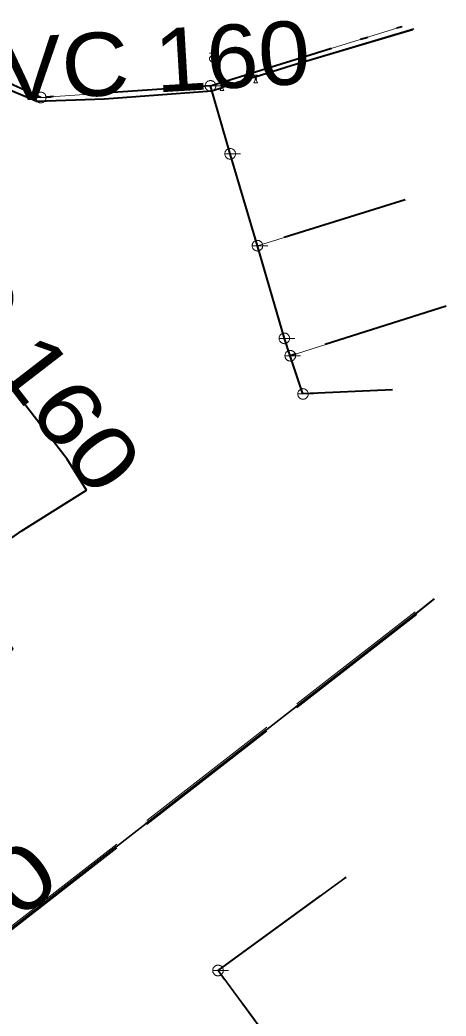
# Model space of a CAD drawing. Extents: x -968691 to -140888, y -1376050 to -879856.
# Drawn here: x -647528.6 to -647447.9, y -1059078.7 to -1058890.1 of the extents above; entities that cross this region are included whole.
import ezdxf
from ezdxf.enums import TextEntityAlignment as Align

# ---------------------------------------------------------------- set-up
doc = ezdxf.new("R2010")
doc.units = 0
doc.header["$LTSCALE"] = 4.8
doc.linetypes.add('DASH_DOUBLE_DOT', pattern=[9.2, 5, -1.2, 0.3, -1.2, 0.3, -1.2])
doc.linetypes.add('LONG_DASHED', pattern=[7.5, 6, -1.5])
doc.layers.add('1', color=7, linetype='Continuous', lineweight=13)

msp = doc.modelspace()

# ---------------------------------------------------------------- hatches: boundary and pattern name
at = {"layer": '1'}
for points in [[(-647490.228, -1058902.72), (-647490.23, -1058902.696), (-647490.237, -1058902.673), (-647490.247, -1058902.651), (-647490.261, -1058902.632), (-647490.279, -1058902.615), (-647490.299, -1058902.602), (-647490.322, -1058902.593), (-647490.345, -1058902.589), (-647490.369, -1058902.588), (-647490.393, -1058902.592), (-647490.416, -1058902.6), (-647490.437, -1058902.612), (-647490.455, -1058902.628), (-647490.47, -1058902.647), (-647490.482, -1058902.668), (-647490.489, -1058902.691), (-647490.492, -1058902.715), (-647490.491, -1058902.739), (-647490.485, -1058902.762), (-647490.475, -1058902.784), (-647490.462, -1058902.804), (-647490.445, -1058902.821), (-647490.425, -1058902.835), (-647490.403, -1058902.845), (-647490.38, -1058902.851), (-647490.356, -1058902.852), (-647490.332, -1058902.849), (-647490.309, -1058902.842), (-647490.288, -1058902.831), (-647490.269, -1058902.816), (-647490.253, -1058902.797), (-647490.241, -1058902.777), (-647490.232, -1058902.754), (-647490.228, -1058902.73)], [(-647483.822, -1058901.276), (-647483.824, -1058901.252), (-647483.831, -1058901.229), (-647483.841, -1058901.207), (-647483.855, -1058901.188), (-647483.873, -1058901.171), (-647483.893, -1058901.158), (-647483.916, -1058901.149), (-647483.939, -1058901.145), (-647483.963, -1058901.144), (-647483.987, -1058901.148), (-647484.01, -1058901.156), (-647484.031, -1058901.168), (-647484.049, -1058901.184), (-647484.064, -1058901.203), (-647484.076, -1058901.224), (-647484.083, -1058901.247), (-647484.086, -1058901.271), (-647484.085, -1058901.295), (-647484.079, -1058901.318), (-647484.069, -1058901.34), (-647484.056, -1058901.36), (-647484.039, -1058901.377), (-647484.019, -1058901.391), (-647483.997, -1058901.401), (-647483.974, -1058901.407), (-647483.95, -1058901.408), (-647483.926, -1058901.405), (-647483.903, -1058901.398), (-647483.882, -1058901.387), (-647483.863, -1058901.372), (-647483.847, -1058901.353), (-647483.835, -1058901.333), (-647483.826, -1058901.31), (-647483.822, -1058901.286)]]:
    msp.add_hatch(color=256, dxfattribs=at).paths.add_polyline_path(points)

# ---------------------------------------------------------------- linework, layer by layer
at = {"layer": '1', "linetype": 'DASH_DOUBLE_DOT', "lineweight": 40}
for p, q in [((-647492.53, -1058902.58), (-647456.24, -1058891.31)), ((-647492.15, -1058897.44), (-647490.36, -1058902.72)), ((-647484.085, -1058900.877), (-647490.306, -1058902.873)), ((-647484.085, -1058900.877), (-647483.954, -1058901.276)), ((-647488.8, -1058915.44), (-647492.53, -1058902.58)), ((-647490.36, -1058902.72), (-647490.306, -1058902.873)), ((-647483.64, -1058932.83), (-647488.8, -1058915.44)), ((-647455.68, -1058924.12), (-647483.64, -1058932.83)), ((-647478.54, -1058950.37), (-647483.64, -1058932.83)), ((-647447.92, -1058944.26), (-647477.42, -1058953.66)), ((-647477.42, -1058953.66), (-647478.54, -1058950.37)), ((-647475.01, -1058960.9), (-647477.42, -1058953.66)), ((-647458.04, -1058960.1), (-647475.01, -1058960.9))]:
    msp.add_line(p, q, dxfattribs=at)
at = {"layer": '1'}
for p, q in [((-647492.53, -1058902.58), (-647456.24, -1058891.31)), ((-647492.709, -1058896.37), (-647491.591, -1058896.37)), ((-647492.15, -1058896.882), (-647492.15, -1058896.37)), ((-647492.15, -1058897.44), (-647490.36, -1058902.72)), ((-647484.085, -1058900.877), (-647483.954, -1058901.276)), ((-647493.538, -1058902.58), (-647490.562, -1058902.58)), ((-647488.8, -1058915.44), (-647492.53, -1058902.58)), ((-647490.36, -1058902.72), (-647490.306, -1058902.873)), ((-647525.668, -1058904.78), (-647522.692, -1058904.78)), ((-647489.808, -1058915.44), (-647486.832, -1058915.44)), ((-647483.64, -1058932.83), (-647488.8, -1058915.44)), ((-647455.68, -1058924.12), (-647483.64, -1058932.83)), ((-647484.648, -1058932.83), (-647481.672, -1058932.83)), ((-647478.54, -1058950.37), (-647483.64, -1058932.83)), ((-647447.92, -1058944.26), (-647477.42, -1058953.66)), ((-647479.548, -1058950.37), (-647476.572, -1058950.37)), ((-647477.42, -1058953.66), (-647478.54, -1058950.37)), ((-647478.428, -1058953.66), (-647475.452, -1058953.66)), ((-647475.01, -1058960.9), (-647477.42, -1058953.66)), ((-647476.018, -1058960.9), (-647473.042, -1058960.9)), ((-647458.04, -1058960.1), (-647475.01, -1058960.9)), ((-647492.108, -1059070.03), (-647489.132, -1059070.03))]:
    msp.add_line(p, q, dxfattribs=at)
at = {"layer": '1', "lineweight": 35}
msp.add_line((-647484.085, -1058900.877), (-647490.306, -1058902.873), dxfattribs=at)
at = {"layer": '1', "linetype": 'LONG_DASHED'}
for p, q in [((-647646.574, -1059152.253), (-647453.794, -1059002.143)), ((-647453.426, -1059002.617), (-647646.206, -1059152.727))]:
    msp.add_line(p, q, dxfattribs=at)
at = {"layer": '1', "linetype": 'DASH_DOUBLE_DOT', "lineweight": 40}
for points in [[(-647484.085, -1058900.877), (-647477.27, -1058898.69), (-647454, -1058891.81)], [(-647492.53, -1058902.58), (-647524.66, -1058904.78), (-647542.07, -1058897.06)], [(-647562.952, -1058916.613), (-647541.39, -1058898.8), (-647525.39, -1058905.47), (-647512.6, -1058905.03), (-647492.29, -1058903.51), (-647490.306, -1058902.873)], [(-647532.092, -1059010.546), (-647529.959, -1059009.197), (-647539.29, -1058995.84), (-647539.66, -1058995.19), (-647539.24, -1058994.56), (-647537.46, -1058993.28), (-647528.4, -1058986.88), (-647516.03, -1058979.12), (-647519.65, -1058973.26), (-647530.64, -1058959.05), (-647535.07, -1058953.43), (-647549.25, -1058935.34), (-647563.74, -1058917.26), (-647562.952, -1058916.613)], [(-647489.07, -1059108.78), (-647472.19, -1059095.7), (-647491.1, -1059070.03), (-647466.86, -1059052.34)]]:
    msp.add_lwpolyline(points, dxfattribs=at)
at = {"layer": '1', "lineweight": 35}
for points in [[(-647484.085, -1058900.877), (-647477.27, -1058898.69), (-647454, -1058891.81)], [(-647562.952, -1058916.613), (-647541.39, -1058898.8), (-647525.39, -1058905.47), (-647512.6, -1058905.03), (-647492.29, -1058903.51), (-647490.306, -1058902.873)], [(-647532.092, -1059010.546), (-647529.959, -1059009.197), (-647539.29, -1058995.84), (-647539.66, -1058995.19), (-647539.24, -1058994.56), (-647537.46, -1058993.28), (-647528.4, -1058986.88), (-647516.03, -1058979.12), (-647519.65, -1058973.26), (-647530.64, -1058959.05), (-647535.07, -1058953.43), (-647549.25, -1058935.34), (-647563.74, -1058917.26), (-647562.952, -1058916.613)], [(-647450.19, -1058999.69), (-647453.61, -1059002.38), (-647646.39, -1059152.49), (-647646.64, -1059152.7), (-647649.55, -1059154.88)], [(-647495.05, -1059100.76), (-647489.07, -1059108.78), (-647472.19, -1059095.7), (-647491.1, -1059070.03), (-647466.86, -1059052.34)]]:
    msp.add_lwpolyline(points, dxfattribs=at)
at = {"layer": '1'}
msp.add_lwpolyline([(-647492.53, -1058902.58), (-647524.66, -1058904.78), (-647542.07, -1058897.06)], dxfattribs=at)
for points in [[(-647491.591, -1058897.44), (-647491.6, -1058897.341), (-647491.627, -1058897.244), (-647491.671, -1058897.154), (-647491.73, -1058897.072), (-647491.802, -1058897.003), (-647491.886, -1058896.948), (-647491.978, -1058896.909), (-647492.076, -1058896.887), (-647492.176, -1058896.882), (-647492.276, -1058896.896), (-647492.371, -1058896.927), (-647492.459, -1058896.975), (-647492.538, -1058897.038), (-647492.603, -1058897.114), (-647492.654, -1058897.2), (-647492.689, -1058897.294), (-647492.707, -1058897.393), (-647492.706, -1058897.493), (-647492.688, -1058897.592), (-647492.652, -1058897.686), (-647492.6, -1058897.771), (-647492.534, -1058897.847), (-647492.455, -1058897.909), (-647492.366, -1058897.956), (-647492.271, -1058897.986), (-647492.171, -1058897.999), (-647492.071, -1058897.994), (-647491.973, -1058897.971), (-647491.881, -1058897.93), (-647491.798, -1058897.875), (-647491.726, -1058897.805), (-647491.668, -1058897.723), (-647491.625, -1058897.632), (-647491.599, -1058897.535)], [(-647484.304, -1058900.526), (-647483.604, -1058900.526), (-647484.304, -1058902.026), (-647483.604, -1058902.026)], [(-647492.53, -1058901.572), (-647492.635, -1058901.578), (-647492.739, -1058901.594), (-647492.841, -1058901.622), (-647492.94, -1058901.66), (-647493.034, -1058901.707), (-647493.122, -1058901.765), (-647493.204, -1058901.831), (-647493.279, -1058901.906), (-647493.345, -1058901.988), (-647493.403, -1058902.076), (-647493.45, -1058902.17), (-647493.488, -1058902.269), (-647493.516, -1058902.371), (-647493.532, -1058902.475), (-647493.538, -1058902.58), (-647493.532, -1058902.685), (-647493.516, -1058902.79), (-647493.488, -1058902.892), (-647493.45, -1058902.99), (-647493.403, -1058903.084), (-647493.345, -1058903.173), (-647493.279, -1058903.255), (-647493.204, -1058903.329), (-647493.122, -1058903.395), (-647493.034, -1058903.453), (-647492.94, -1058903.501), (-647492.841, -1058903.539), (-647492.739, -1058903.566), (-647492.635, -1058903.582), (-647492.53, -1058903.588), (-647492.425, -1058903.582), (-647492.32, -1058903.566), (-647492.218, -1058903.539), (-647492.12, -1058903.501), (-647492.026, -1058903.453), (-647491.937, -1058903.395), (-647491.855, -1058903.329), (-647491.781, -1058903.255), (-647491.715, -1058903.173), (-647491.657, -1058903.084), (-647491.609, -1058902.99), (-647491.571, -1058902.892), (-647491.544, -1058902.79), (-647491.528, -1058902.685), (-647491.522, -1058902.58), (-647491.528, -1058902.475), (-647491.544, -1058902.371), (-647491.571, -1058902.269), (-647491.609, -1058902.17), (-647491.657, -1058902.076), (-647491.715, -1058901.988), (-647491.781, -1058901.906), (-647491.855, -1058901.831), (-647491.937, -1058901.765), (-647492.026, -1058901.707), (-647492.12, -1058901.66), (-647492.218, -1058901.622), (-647492.32, -1058901.594), (-647492.425, -1058901.578)], [(-647490.71, -1058901.97), (-647490.01, -1058901.97), (-647490.71, -1058903.47), (-647490.01, -1058903.47)], [(-647490.228, -1058902.72), (-647490.23, -1058902.696), (-647490.237, -1058902.673), (-647490.247, -1058902.651), (-647490.261, -1058902.632), (-647490.279, -1058902.615), (-647490.299, -1058902.602), (-647490.322, -1058902.593), (-647490.345, -1058902.589), (-647490.369, -1058902.588), (-647490.393, -1058902.592), (-647490.416, -1058902.6), (-647490.437, -1058902.612), (-647490.455, -1058902.628), (-647490.47, -1058902.647), (-647490.482, -1058902.668), (-647490.489, -1058902.691), (-647490.492, -1058902.715), (-647490.491, -1058902.739), (-647490.485, -1058902.762), (-647490.475, -1058902.784), (-647490.462, -1058902.804), (-647490.445, -1058902.821), (-647490.425, -1058902.835), (-647490.403, -1058902.845), (-647490.38, -1058902.851), (-647490.356, -1058902.852), (-647490.332, -1058902.849), (-647490.309, -1058902.842), (-647490.288, -1058902.831), (-647490.269, -1058902.816), (-647490.253, -1058902.797), (-647490.241, -1058902.777), (-647490.232, -1058902.754), (-647490.228, -1058902.73)], [(-647483.822, -1058901.276), (-647483.824, -1058901.252), (-647483.831, -1058901.229), (-647483.841, -1058901.207), (-647483.855, -1058901.188), (-647483.873, -1058901.171), (-647483.893, -1058901.158), (-647483.916, -1058901.149), (-647483.939, -1058901.145), (-647483.963, -1058901.144), (-647483.987, -1058901.148), (-647484.01, -1058901.156), (-647484.031, -1058901.168), (-647484.049, -1058901.184), (-647484.064, -1058901.203), (-647484.076, -1058901.224), (-647484.083, -1058901.247), (-647484.086, -1058901.271), (-647484.085, -1058901.295), (-647484.079, -1058901.318), (-647484.069, -1058901.34), (-647484.056, -1058901.36), (-647484.039, -1058901.377), (-647484.019, -1058901.391), (-647483.997, -1058901.401), (-647483.974, -1058901.407), (-647483.95, -1058901.408), (-647483.926, -1058901.405), (-647483.903, -1058901.398), (-647483.882, -1058901.387), (-647483.863, -1058901.372), (-647483.847, -1058901.353), (-647483.835, -1058901.333), (-647483.826, -1058901.31), (-647483.822, -1058901.286)], [(-647524.66, -1058903.772), (-647524.765, -1058903.778), (-647524.869, -1058903.794), (-647524.971, -1058903.822), (-647525.07, -1058903.86), (-647525.164, -1058903.907), (-647525.252, -1058903.965), (-647525.334, -1058904.031), (-647525.409, -1058904.106), (-647525.475, -1058904.188), (-647525.533, -1058904.276), (-647525.58, -1058904.37), (-647525.618, -1058904.469), (-647525.646, -1058904.571), (-647525.662, -1058904.675), (-647525.668, -1058904.78), (-647525.662, -1058904.885), (-647525.646, -1058904.99), (-647525.618, -1058905.092), (-647525.58, -1058905.19), (-647525.533, -1058905.284), (-647525.475, -1058905.373), (-647525.409, -1058905.455), (-647525.334, -1058905.529), (-647525.252, -1058905.595), (-647525.164, -1058905.653), (-647525.07, -1058905.701), (-647524.971, -1058905.739), (-647524.869, -1058905.766), (-647524.765, -1058905.782), (-647524.66, -1058905.788), (-647524.555, -1058905.782), (-647524.45, -1058905.766), (-647524.348, -1058905.739), (-647524.25, -1058905.701), (-647524.156, -1058905.653), (-647524.067, -1058905.595), (-647523.985, -1058905.529), (-647523.911, -1058905.455), (-647523.845, -1058905.373), (-647523.787, -1058905.284), (-647523.739, -1058905.19), (-647523.701, -1058905.092), (-647523.674, -1058904.99), (-647523.658, -1058904.885), (-647523.652, -1058904.78), (-647523.658, -1058904.675), (-647523.674, -1058904.571), (-647523.701, -1058904.469), (-647523.739, -1058904.37), (-647523.787, -1058904.276), (-647523.845, -1058904.188), (-647523.911, -1058904.106), (-647523.985, -1058904.031), (-647524.067, -1058903.965), (-647524.156, -1058903.907), (-647524.25, -1058903.86), (-647524.348, -1058903.822), (-647524.45, -1058903.794), (-647524.555, -1058903.778)], [(-647488.8, -1058914.432), (-647488.905, -1058914.438), (-647489.009, -1058914.454), (-647489.111, -1058914.482), (-647489.21, -1058914.52), (-647489.304, -1058914.567), (-647489.392, -1058914.625), (-647489.474, -1058914.691), (-647489.549, -1058914.766), (-647489.615, -1058914.848), (-647489.673, -1058914.936), (-647489.72, -1058915.03), (-647489.758, -1058915.129), (-647489.786, -1058915.231), (-647489.802, -1058915.335), (-647489.808, -1058915.44), (-647489.802, -1058915.545), (-647489.786, -1058915.65), (-647489.758, -1058915.752), (-647489.72, -1058915.85), (-647489.673, -1058915.944), (-647489.615, -1058916.033), (-647489.549, -1058916.115), (-647489.474, -1058916.189), (-647489.392, -1058916.255), (-647489.304, -1058916.313), (-647489.21, -1058916.361), (-647489.111, -1058916.399), (-647489.009, -1058916.426), (-647488.905, -1058916.442), (-647488.8, -1058916.448), (-647488.695, -1058916.442), (-647488.59, -1058916.426), (-647488.488, -1058916.399), (-647488.39, -1058916.361), (-647488.296, -1058916.313), (-647488.207, -1058916.255), (-647488.125, -1058916.189), (-647488.051, -1058916.115), (-647487.985, -1058916.033), (-647487.927, -1058915.944), (-647487.879, -1058915.85), (-647487.841, -1058915.752), (-647487.814, -1058915.65), (-647487.798, -1058915.545), (-647487.792, -1058915.44), (-647487.798, -1058915.335), (-647487.814, -1058915.231), (-647487.841, -1058915.129), (-647487.879, -1058915.03), (-647487.927, -1058914.936), (-647487.985, -1058914.848), (-647488.051, -1058914.766), (-647488.125, -1058914.691), (-647488.207, -1058914.625), (-647488.296, -1058914.567), (-647488.39, -1058914.52), (-647488.488, -1058914.482), (-647488.59, -1058914.454), (-647488.695, -1058914.438)], [(-647483.64, -1058931.822), (-647483.745, -1058931.828), (-647483.849, -1058931.844), (-647483.951, -1058931.872), (-647484.05, -1058931.91), (-647484.144, -1058931.957), (-647484.232, -1058932.015), (-647484.314, -1058932.081), (-647484.389, -1058932.156), (-647484.455, -1058932.238), (-647484.513, -1058932.326), (-647484.56, -1058932.42), (-647484.598, -1058932.519), (-647484.626, -1058932.621), (-647484.642, -1058932.725), (-647484.648, -1058932.83), (-647484.642, -1058932.935), (-647484.626, -1058933.04), (-647484.598, -1058933.142), (-647484.56, -1058933.24), (-647484.513, -1058933.334), (-647484.455, -1058933.423), (-647484.389, -1058933.505), (-647484.314, -1058933.579), (-647484.232, -1058933.645), (-647484.144, -1058933.703), (-647484.05, -1058933.751), (-647483.951, -1058933.789), (-647483.849, -1058933.816), (-647483.745, -1058933.832), (-647483.64, -1058933.838), (-647483.535, -1058933.832), (-647483.43, -1058933.816), (-647483.328, -1058933.789), (-647483.23, -1058933.751), (-647483.136, -1058933.703), (-647483.047, -1058933.645), (-647482.965, -1058933.579), (-647482.891, -1058933.505), (-647482.825, -1058933.423), (-647482.767, -1058933.334), (-647482.719, -1058933.24), (-647482.681, -1058933.142), (-647482.654, -1058933.04), (-647482.638, -1058932.935), (-647482.632, -1058932.83), (-647482.638, -1058932.725), (-647482.654, -1058932.621), (-647482.681, -1058932.519), (-647482.719, -1058932.42), (-647482.767, -1058932.326), (-647482.825, -1058932.238), (-647482.891, -1058932.156), (-647482.965, -1058932.081), (-647483.047, -1058932.015), (-647483.136, -1058931.957), (-647483.23, -1058931.91), (-647483.328, -1058931.872), (-647483.43, -1058931.844), (-647483.535, -1058931.828)], [(-647478.54, -1058949.362), (-647478.645, -1058949.368), (-647478.749, -1058949.384), (-647478.851, -1058949.412), (-647478.95, -1058949.45), (-647479.044, -1058949.497), (-647479.132, -1058949.555), (-647479.214, -1058949.621), (-647479.289, -1058949.696), (-647479.355, -1058949.778), (-647479.413, -1058949.866), (-647479.46, -1058949.96), (-647479.498, -1058950.059), (-647479.526, -1058950.161), (-647479.542, -1058950.265), (-647479.548, -1058950.37), (-647479.542, -1058950.475), (-647479.526, -1058950.58), (-647479.498, -1058950.682), (-647479.46, -1058950.78), (-647479.413, -1058950.874), (-647479.355, -1058950.963), (-647479.289, -1058951.045), (-647479.214, -1058951.119), (-647479.132, -1058951.185), (-647479.044, -1058951.243), (-647478.95, -1058951.291), (-647478.851, -1058951.329), (-647478.749, -1058951.356), (-647478.645, -1058951.372), (-647478.54, -1058951.378), (-647478.435, -1058951.372), (-647478.33, -1058951.356), (-647478.228, -1058951.329), (-647478.13, -1058951.291), (-647478.036, -1058951.243), (-647477.947, -1058951.185), (-647477.865, -1058951.119), (-647477.791, -1058951.045), (-647477.725, -1058950.963), (-647477.667, -1058950.874), (-647477.619, -1058950.78), (-647477.581, -1058950.682), (-647477.554, -1058950.58), (-647477.538, -1058950.475), (-647477.532, -1058950.37), (-647477.538, -1058950.265), (-647477.554, -1058950.161), (-647477.581, -1058950.059), (-647477.619, -1058949.96), (-647477.667, -1058949.866), (-647477.725, -1058949.778), (-647477.791, -1058949.696), (-647477.865, -1058949.621), (-647477.947, -1058949.555), (-647478.036, -1058949.497), (-647478.13, -1058949.45), (-647478.228, -1058949.412), (-647478.33, -1058949.384), (-647478.435, -1058949.368)], [(-647477.42, -1058952.652), (-647477.525, -1058952.658), (-647477.629, -1058952.674), (-647477.731, -1058952.702), (-647477.83, -1058952.74), (-647477.924, -1058952.787), (-647478.012, -1058952.845), (-647478.094, -1058952.911), (-647478.169, -1058952.986), (-647478.235, -1058953.068), (-647478.293, -1058953.156), (-647478.34, -1058953.25), (-647478.378, -1058953.349), (-647478.406, -1058953.451), (-647478.422, -1058953.555), (-647478.428, -1058953.66), (-647478.422, -1058953.765), (-647478.406, -1058953.87), (-647478.378, -1058953.972), (-647478.34, -1058954.07), (-647478.293, -1058954.164), (-647478.235, -1058954.253), (-647478.169, -1058954.335), (-647478.094, -1058954.409), (-647478.012, -1058954.475), (-647477.924, -1058954.533), (-647477.83, -1058954.581), (-647477.731, -1058954.619), (-647477.629, -1058954.646), (-647477.525, -1058954.662), (-647477.42, -1058954.668), (-647477.315, -1058954.662), (-647477.21, -1058954.646), (-647477.108, -1058954.619), (-647477.01, -1058954.581), (-647476.916, -1058954.533), (-647476.827, -1058954.475), (-647476.745, -1058954.409), (-647476.671, -1058954.335), (-647476.605, -1058954.253), (-647476.547, -1058954.164), (-647476.499, -1058954.07), (-647476.461, -1058953.972), (-647476.434, -1058953.87), (-647476.418, -1058953.765), (-647476.412, -1058953.66), (-647476.418, -1058953.555), (-647476.434, -1058953.451), (-647476.461, -1058953.349), (-647476.499, -1058953.25), (-647476.547, -1058953.156), (-647476.605, -1058953.068), (-647476.671, -1058952.986), (-647476.745, -1058952.911), (-647476.827, -1058952.845), (-647476.916, -1058952.787), (-647477.01, -1058952.74), (-647477.108, -1058952.702), (-647477.21, -1058952.674), (-647477.315, -1058952.658)], [(-647475.01, -1058959.892), (-647475.115, -1058959.898), (-647475.219, -1058959.914), (-647475.321, -1058959.942), (-647475.42, -1058959.98), (-647475.514, -1058960.027), (-647475.602, -1058960.085), (-647475.684, -1058960.151), (-647475.759, -1058960.226), (-647475.825, -1058960.308), (-647475.883, -1058960.396), (-647475.93, -1058960.49), (-647475.968, -1058960.589), (-647475.996, -1058960.691), (-647476.012, -1058960.795), (-647476.018, -1058960.9), (-647476.012, -1058961.005), (-647475.996, -1058961.11), (-647475.968, -1058961.212), (-647475.93, -1058961.31), (-647475.883, -1058961.404), (-647475.825, -1058961.493), (-647475.759, -1058961.575), (-647475.684, -1058961.649), (-647475.602, -1058961.715), (-647475.514, -1058961.773), (-647475.42, -1058961.821), (-647475.321, -1058961.859), (-647475.219, -1058961.886), (-647475.115, -1058961.902), (-647475.01, -1058961.908), (-647474.905, -1058961.902), (-647474.8, -1058961.886), (-647474.698, -1058961.859), (-647474.6, -1058961.821), (-647474.506, -1058961.773), (-647474.417, -1058961.715), (-647474.335, -1058961.649), (-647474.261, -1058961.575), (-647474.195, -1058961.493), (-647474.137, -1058961.404), (-647474.089, -1058961.31), (-647474.051, -1058961.212), (-647474.024, -1058961.11), (-647474.008, -1058961.005), (-647474.002, -1058960.9), (-647474.008, -1058960.795), (-647474.024, -1058960.691), (-647474.051, -1058960.589), (-647474.089, -1058960.49), (-647474.137, -1058960.396), (-647474.195, -1058960.308), (-647474.261, -1058960.226), (-647474.335, -1058960.151), (-647474.417, -1058960.085), (-647474.506, -1058960.027), (-647474.6, -1058959.98), (-647474.698, -1058959.942), (-647474.8, -1058959.914), (-647474.905, -1058959.898)], [(-647491.1, -1059069.022), (-647491.205, -1059069.028), (-647491.309, -1059069.044), (-647491.411, -1059069.072), (-647491.51, -1059069.11), (-647491.604, -1059069.157), (-647491.692, -1059069.215), (-647491.774, -1059069.281), (-647491.849, -1059069.356), (-647491.915, -1059069.438), (-647491.973, -1059069.526), (-647492.02, -1059069.62), (-647492.058, -1059069.719), (-647492.086, -1059069.821), (-647492.102, -1059069.925), (-647492.108, -1059070.03), (-647492.102, -1059070.135), (-647492.086, -1059070.24), (-647492.058, -1059070.342), (-647492.02, -1059070.44), (-647491.973, -1059070.534), (-647491.915, -1059070.623), (-647491.849, -1059070.705), (-647491.774, -1059070.779), (-647491.692, -1059070.845), (-647491.604, -1059070.903), (-647491.51, -1059070.951), (-647491.411, -1059070.989), (-647491.309, -1059071.016), (-647491.205, -1059071.032), (-647491.1, -1059071.038), (-647490.995, -1059071.032), (-647490.89, -1059071.016), (-647490.788, -1059070.989), (-647490.69, -1059070.951), (-647490.596, -1059070.903), (-647490.507, -1059070.845), (-647490.425, -1059070.779), (-647490.351, -1059070.705), (-647490.285, -1059070.623), (-647490.227, -1059070.534), (-647490.179, -1059070.44), (-647490.141, -1059070.342), (-647490.114, -1059070.24), (-647490.098, -1059070.135), (-647490.092, -1059070.03), (-647490.098, -1059069.925), (-647490.114, -1059069.821), (-647490.141, -1059069.719), (-647490.179, -1059069.62), (-647490.227, -1059069.526), (-647490.285, -1059069.438), (-647490.351, -1059069.356), (-647490.425, -1059069.281), (-647490.507, -1059069.215), (-647490.596, -1059069.157), (-647490.69, -1059069.11), (-647490.788, -1059069.072), (-647490.89, -1059069.044), (-647490.995, -1059069.028)]]:
    msp.add_lwpolyline(points, close=True, dxfattribs=at)
at = {"layer": '1', "linetype": 'LONG_DASHED', "lineweight": 40}
msp.add_lwpolyline([(-647450.19, -1058999.69), (-647453.61, -1059002.38), (-647646.39, -1059152.49), (-647646.64, -1059152.7), (-647649.55, -1059154.88)], dxfattribs=at)

# ---------------------------------------------------------------- texts
at = {"layer": '1'}
for s, rotation, width, p in [('PVC 160', 3.389, 1.1, (-647508.625, -1058904.176)), ('PVC 160', 307.641, 1.2, (-647537.792, -1058950.411)), ('PE 560', 37.914, 1.25, (-647546.179, -1059074.073))]:
    msp.add_text(s, height=12, rotation=rotation, dxfattribs=dict(at, width=width)).set_placement(p, align=Align.CENTER)

doc.saveas('drawing.dxf')
